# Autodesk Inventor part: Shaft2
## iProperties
Created: 2007-11
Part Number: Shaft2
Material: Steel
Document SubType Name: Modeling
Designer: CM
Density: 7.85 g/cm^3
Mass: 718.372 g
Surface Area: 157.281 cm^2
Volume: 91.5124 cm^3
CustomPartVersion: 1
Author: CM
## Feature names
1. Revolution1
2. Chamfer1
3. Chamfer2
4. Chamfer3
5. Fillet1
6. Chamfer4
7. Chamfer5
